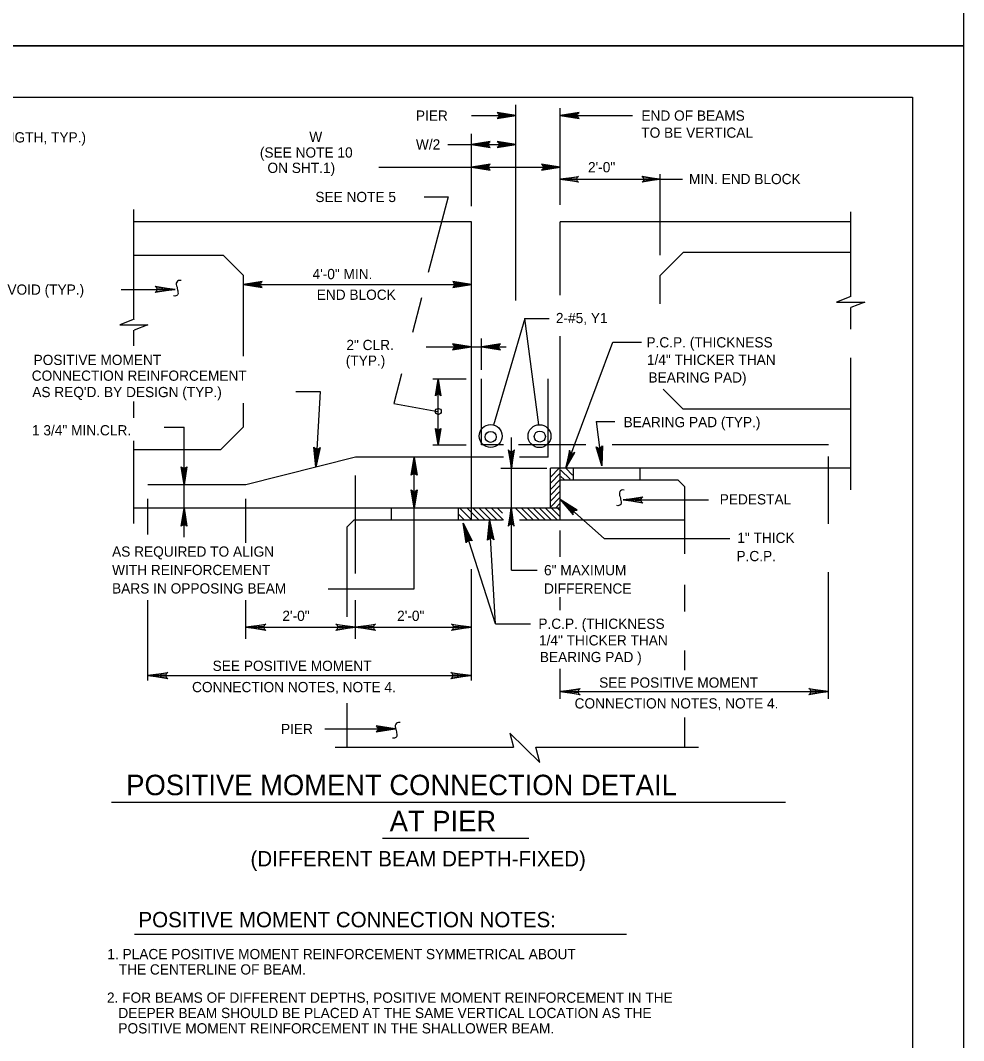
# Model space of a CAD drawing. Extents: x 641517 to 642372, y 298537 to 300319.
# Drawn here: x 642081.6 to 642358, y 299433 to 299732.1 of the extents above; entities that cross this region are included whole.
import ezdxf

# ---------------------------------------------------------------- set-up
doc = ezdxf.new("R2010")
doc.units = 0
for name, color, linetype in [('1', 7, 'Continuous'), ('2', 7, 'Continuous'), ('3', 7, 'Continuous'), ('PLT-BNDY', 7, 'Continuous')]:
    doc.layers.add(name, color=color, linetype=linetype)

msp = doc.modelspace()

# ---------------------------------------------------------------- linework, layer by layer
at = {"layer": '1'}
for p, q in [((642226.83, 299649.99), (642226.83, 299707.41)), ((642213.81, 299589.15), (642213.81, 299673.03)), ((642239.85, 299651.6), (642239.85, 299673.03)), ((642233.55, 299613.6), (642229.43, 299644.7)), ((642239.85, 299585.63), (642239.85, 299639.58)), ((642243.69, 299597.3), (642243.69, 299600.82)), ((642210.01, 299585.63), (642210.01, 299589.15)), ((642213.81, 299585.63), (642213.81, 299589.15)), ((642233.85, 299514.6), (642225.01, 299523.13)), ((642225.01, 299523.13), (642226.17, 299519.07)), ((642233.85, 299514.6), (642232.66, 299519.07))]:
    msp.add_line(p, q, dxfattribs=at)
for points in [[(642128.69, 299655.9), (642127.89, 299655.83), (642127.45, 299655.42), (642127.28, 299654.66), (642127.5, 299653.94), (642127.65, 299653.18), (642127.78, 299652.42), (642127.69, 299651.66), (642127.13, 299651.33), (642126.52, 299651.33)], [(642258.57, 299594.44), (642257.76, 299594.38), (642257.33, 299593.96), (642257.15, 299593.2), (642257.37, 299592.48), (642257.52, 299591.72), (642257.65, 299590.96), (642257.57, 299590.2), (642257, 299589.87), (642256.39, 299589.87)], [(642192.86, 299526.3), (642192.05, 299526.23), (642191.62, 299525.82), (642191.44, 299525.06), (642191.66, 299524.34), (642191.81, 299523.58), (642191.94, 299522.82), (642191.86, 299522.06), (642191.29, 299521.73), (642190.68, 299521.73)]]:
    msp.add_spline(points, degree=3, dxfattribs=at)
at = {"layer": '2'}
for p, q in [((641557.05, 299709.62), (642343.05, 299709.62)), ((642343.05, 299709.62), (642343.05, 299145.62)), ((642239.85, 299678.05), (642239.85, 299706.36)), ((642213.81, 299704.23), (642226.83, 299704.23)), ((642239.85, 299704.29), (642261.01, 299704.29)), ((642213.81, 299677.62), (642213.81, 299698.86)), ((642206.84, 299695.76), (642213.81, 299695.76)), ((642213.81, 299695.76), (642226.83, 299695.76)), ((642186.65, 299689.09), (642213.81, 299689.09)), ((642213.81, 299689.09), (642239.85, 299689.09)), ((642239.85, 299685.55), (642269.16, 299685.55)), ((642269.16, 299663.28), (642269.16, 299687.01)), ((642269.16, 299685.55), (642275.68, 299685.55)), ((642199.98, 299680.36), (642206.95, 299680.36)), ((642206.95, 299680.36), (642201.13, 299658.24)), ((642114.85, 299644.49), (642114.85, 299676.71)), ((642325.02, 299651.18), (642325.02, 299675.97)), ((642213.81, 299673.03), (642114.85, 299673.03)), ((642325.02, 299673.03), (642239.85, 299673.03)), ((642141.1, 299663.19), (642114.85, 299663.19)), ((642275.88, 299664.05), (642269.16, 299657.33)), ((642325.02, 299664.05), (642275.88, 299664.05)), ((642111.18, 299653.26), (642126.94, 299653.26)), ((642146.96, 299654.66), (642213.81, 299654.66)), ((642199.17, 299650.79), (642196.5, 299640.63)), ((642325.02, 299651.18), (642320.84, 299649.54)), ((642320.84, 299649.54), (642329.08, 299649.54)), ((642329.08, 299649.54), (642325.02, 299647.96)), ((642324.97, 299641.62), (642324.97, 299647.96)), ((642114.92, 299644.49), (642110.74, 299642.85)), ((642229.43, 299644.7), (642220.31, 299613.49)), ((642229.43, 299644.7), (642236.55, 299644.7)), ((642110.74, 299642.85), (642118.98, 299642.85)), ((642114.85, 299636.69), (642114.85, 299641.27)), ((642118.98, 299642.85), (642114.92, 299641.27)), ((642216.78, 299629.66), (642216.78, 299638.89)), ((642241.5, 299600.82), (642255.25, 299637.78)), ((642255.25, 299637.78), (642263.69, 299637.78)), ((642200.49, 299636.42), (642213.81, 299636.42)), ((642213.81, 299636.42), (642224, 299636.42)), ((642324.97, 299594.5), (642324.97, 299633.19)), ((642193.32, 299628.52), (642191.02, 299619.78)), ((642202.46, 299627), (642212.23, 299627)), ((642204.07, 299607.67), (642204.07, 299626.95)), ((642216.78, 299607.67), (642216.78, 299627)), ((642236.32, 299604.1), (642236.32, 299627)), ((642162.31, 299623.33), (642169.49, 299623.33)), ((642169.49, 299623.33), (642168.19, 299601.13)), ((642114.85, 299615.56), (642114.85, 299620.38)), ((642191.02, 299619.78), (642203.91, 299617.49)), ((642324.97, 299618.12), (642275.88, 299618.12)), ((642250.32, 299614.51), (642255.85, 299614.51)), ((642250.32, 299614.51), (642252, 299601.49)), ((642123.72, 299612.84), (642129.55, 299612.84)), ((642129.55, 299595.94), (642129.55, 299612.84)), ((642146.96, 299612.92), (642140.24, 299606.2)), ((642114.85, 299584.59), (642114.85, 299608.9)), ((642202.46, 299607.67), (642212.23, 299607.67)), ((642223.2, 299607.67), (642216.78, 299607.67)), ((642225.5, 299600.73), (642225.5, 299609.81)), ((642247.28, 299607.67), (642227.6, 299607.67)), ((642318.49, 299607.67), (642255, 299607.67)), ((642140.24, 299606.2), (642114.85, 299606.2)), ((642179.86, 299604.1), (642147.71, 299595.94)), ((642223.2, 299604.1), (642179.86, 299604.1)), ((642197, 299589.15), (642197, 299604.1)), ((642236.32, 299604.1), (642227.92, 299604.1)), ((642318.49, 299584.54), (642318.49, 299604.28)), ((642179.86, 299569.98), (642179.86, 299598.7)), ((642222.43, 299600.82), (642235.91, 299600.82)), ((642225.5, 299587.94), (642225.5, 299600.73)), ((642236.93, 299589.15), (642236.93, 299600.82)), ((642324.97, 299600.82), (642236.93, 299600.82)), ((642239.55, 299600.82), (642236.93, 299598.2)), ((642239.85, 299599.35), (642236.93, 299596.43)), ((642242.69, 299597.62), (642240.01, 299600.3)), ((642243.41, 299598.83), (642241.42, 299600.82)), ((642263.29, 299597.3), (642263.29, 299600.82)), ((642147.71, 299595.94), (642118.99, 299595.94)), ((642129.55, 299589.15), (642129.55, 299595.94)), ((642239.85, 299597.56), (642236.93, 299594.63)), ((642239.85, 299595.91), (642236.93, 299592.98)), ((642274.36, 299597.3), (642239.85, 299597.3)), ((642240.95, 299597.48), (642240.04, 299598.39)), ((642276.31, 299595.34), (642274.36, 299597.3)), ((642239.85, 299594.14), (642236.93, 299591.22)), ((642276.31, 299575.69), (642276.31, 299595.34)), ((642118.99, 299581.37), (642118.99, 299591.83)), ((642147.71, 299578.99), (642147.71, 299591.83)), ((642239.85, 299592.37), (642236.63, 299589.15)), ((642239.85, 299590.61), (642238.4, 299589.15)), ((642239.85, 299591.7), (642252.69, 299580.18)), ((642258.24, 299591.54), (642283.31, 299591.54)), ((642239.85, 299589.15), (642114.85, 299589.15)), ((642129.55, 299580.65), (642129.55, 299589.15)), ((642190.38, 299585.63), (642190.38, 299589.15)), ((642197, 299565.45), (642197, 299589.15)), ((642211.79, 299585.63), (642210.14, 299587.27)), ((642213.93, 299585.63), (642210.52, 299589.04)), ((642216.08, 299585.63), (642212.55, 299589.15)), ((642217.84, 299585.63), (642214.32, 299589.15)), ((642219.61, 299585.63), (642216.09, 299589.15)), ((642221.38, 299585.63), (642217.86, 299589.15)), ((642223.15, 299585.63), (642219.63, 299589.15)), ((642222.89, 299587.66), (642221.39, 299589.15)), ((642225.5, 299570.98), (642225.5, 299587.94)), ((642230.22, 299585.63), (642226.7, 299589.15)), ((642231.98, 299585.63), (642228.46, 299589.15)), ((642233.75, 299585.63), (642230.23, 299589.15)), ((642235.52, 299585.63), (642232, 299589.15)), ((642237.29, 299585.63), (642233.77, 299589.15)), ((642239.06, 299585.63), (642235.54, 299589.15)), ((642239.85, 299586.6), (642237.3, 299589.15)), ((642239.85, 299588.37), (642239.07, 299589.15)), ((642177.35, 299583.67), (642179.31, 299585.63)), ((642177.35, 299557.28), (642177.35, 299583.67)), ((642222.88, 299585.63), (642179.31, 299585.63)), ((642220.89, 299555.22), (642211.35, 299584.75)), ((642220.89, 299555.22), (642219.13, 299585.63)), ((642276.31, 299585.63), (642227.92, 299585.63)), ((642239.85, 299574.81), (642239.85, 299582.6)), ((642252.69, 299580.18), (642289.49, 299580.18)), ((642213.81, 299538.61), (642213.81, 299571.23)), ((642225.5, 299570.98), (642233.07, 299570.98)), ((642318.49, 299533.24), (642318.49, 299570.4)), ((642276.31, 299558.78), (642276.31, 299566.65)), ((642171.84, 299565.45), (642197, 299565.45)), ((642239.85, 299559.21), (642239.85, 299563.07)), ((642118.99, 299538.61), (642118.99, 299562.13)), ((642147.71, 299550.84), (642147.71, 299562.13)), ((642179.86, 299550.84), (642179.86, 299562.13)), ((642147.71, 299554.21), (642179.86, 299554.21)), ((642179.86, 299554.21), (642213.81, 299554.21)), ((642220.89, 299555.22), (642231.11, 299555.22)), ((642276.31, 299541.61), (642276.31, 299547.41)), ((642239.85, 299533.24), (642239.85, 299542.04)), ((642118.99, 299540.05), (642213.6, 299540.05)), ((642239.85, 299535.33), (642318.49, 299535.33)), ((642177.35, 299519.07), (642177.35, 299531.95)), ((642276.31, 299519.07), (642276.31, 299527.73)), ((642170.86, 299524.43), (642191.41, 299524.43)), ((642173.82, 299519.07), (642226.17, 299519.07)), ((642232.66, 299519.07), (642280.38, 299519.07)), ((642108.26, 299502.92), (642305.88, 299502.92)), ((642187.71, 299492.33), (642230.64, 299492.33)), ((642115, 299464.27), (642259.25, 299464.27))]:
    msp.add_line(p, q, dxfattribs=at)
for points in [[(642221.6, 299703.57), (642221.8, 299703.95), (642226.83, 299704.23), (642221.6, 299703.57), (642221.33, 299703.34), (642226.83, 299704.23), (642221.8, 299704.47), (642221.62, 299704.85), (642226.83, 299704.23), (642221.33, 299705.1), (642221.62, 299704.85)], [(642245.08, 299704.94), (642244.89, 299704.56), (642239.85, 299704.29), (642245.08, 299704.94), (642245.35, 299705.17), (642239.85, 299704.29), (642244.89, 299704.04), (642245.07, 299703.66), (642239.85, 299704.29), (642245.35, 299703.41), (642245.07, 299703.66)], [(642219.04, 299696.42), (642218.85, 299696.04), (642213.81, 299695.76), (642219.04, 299696.42), (642219.31, 299696.64), (642213.81, 299695.76), (642218.84, 299695.51), (642219.03, 299695.13), (642213.81, 299695.76), (642219.31, 299694.88), (642219.03, 299695.13)], [(642221.6, 299695.1), (642221.8, 299695.48), (642226.83, 299695.76), (642221.6, 299695.1), (642221.33, 299694.87), (642226.83, 299695.76), (642221.8, 299696.01), (642221.62, 299696.38), (642226.83, 299695.76), (642221.33, 299696.63), (642221.62, 299696.38)], [(642219.04, 299689.75), (642218.85, 299689.37), (642213.81, 299689.09), (642219.04, 299689.75), (642219.31, 299689.98), (642213.81, 299689.09), (642218.84, 299688.84), (642219.03, 299688.47), (642213.81, 299689.09), (642219.31, 299688.22), (642219.03, 299688.47)], [(642234.62, 299688.43), (642234.82, 299688.81), (642239.85, 299689.09), (642234.62, 299688.43), (642234.35, 299688.21), (642239.85, 299689.09), (642234.82, 299689.34), (642234.64, 299689.72), (642239.85, 299689.09), (642234.35, 299689.97), (642234.64, 299689.72)], [(642244.93, 299684.92), (642244.74, 299685.28), (642239.85, 299685.55), (642244.93, 299684.92), (642245.19, 299684.69), (642239.85, 299685.55), (642244.73, 299685.8), (642244.91, 299686.16), (642239.85, 299685.55), (642245.19, 299686.4), (642244.91, 299686.16)], [(642264.08, 299686.19), (642264.27, 299685.82), (642269.16, 299685.55), (642264.08, 299686.19), (642263.82, 299686.41), (642269.16, 299685.55), (642264.28, 299685.31), (642264.1, 299684.95), (642269.16, 299685.55), (642263.82, 299684.71), (642264.1, 299684.95)], [(642152.2, 299655.32), (642152, 299654.94), (642146.96, 299654.66), (642152.2, 299655.32), (642152.46, 299655.55), (642146.96, 299654.66), (642152, 299654.41), (642152.18, 299654.04), (642146.96, 299654.66), (642152.46, 299653.79), (642152.18, 299654.04)], [(642208.58, 299654), (642208.78, 299654.38), (642213.81, 299654.66), (642208.58, 299654), (642208.31, 299653.77), (642213.81, 299654.66), (642208.78, 299654.91), (642208.6, 299655.28), (642213.81, 299654.66), (642208.31, 299655.54), (642208.6, 299655.28)], [(642121.41, 299653.96), (642121.61, 299653.56), (642126.94, 299653.26), (642121.41, 299653.96), (642121.12, 299654.2), (642126.94, 299653.26), (642121.62, 299653), (642121.42, 299652.6), (642126.94, 299653.26), (642121.12, 299652.34), (642121.42, 299652.6)], [(642208.47, 299635.77), (642208.67, 299636.15), (642213.7, 299636.43), (642208.47, 299635.77), (642208.2, 299635.55), (642213.7, 299636.43), (642208.67, 299636.68), (642208.49, 299637.06), (642213.7, 299636.43), (642208.2, 299637.31), (642208.49, 299637.06)], [(642222.07, 299637.06), (642221.88, 299636.69), (642216.84, 299636.41), (642222.07, 299637.06), (642222.34, 299637.29), (642216.84, 299636.41), (642221.87, 299636.16), (642222.06, 299635.78), (642216.84, 299636.41), (642222.34, 299635.53), (642222.06, 299635.78)], [(642203.49, 299622.34), (642203.83, 299622.51), (642204.07, 299626.95), (642203.49, 299622.34), (642203.29, 299622.1), (642204.07, 299626.95), (642204.29, 299622.52), (642204.62, 299622.35), (642204.07, 299626.95), (642204.84, 299622.1), (642204.62, 299622.35)], [(642204.65, 299612.28), (642204.32, 299612.11), (642204.07, 299607.67), (642204.65, 299612.28), (642204.85, 299612.52), (642204.07, 299607.67), (642203.85, 299612.11), (642203.52, 299612.27), (642204.07, 299607.67), (642203.3, 299612.52), (642203.52, 299612.27)], [(642169.21, 299606.62), (642168.8, 299606.44), (642168.19, 299601.13), (642169.21, 299606.62), (642169.47, 299606.89), (642168.19, 299601.13), (642168.24, 299606.47), (642167.85, 299606.68), (642168.19, 299601.13), (642167.61, 299607), (642167.85, 299606.68)], [(642224.84, 299605.96), (642225.22, 299605.77), (642225.5, 299600.73), (642224.84, 299605.96), (642224.61, 299606.23), (642225.5, 299600.73), (642225.75, 299605.76), (642226.12, 299605.95), (642225.5, 299600.73), (642226.37, 299606.23), (642226.12, 299605.95)], [(642242.66, 299605.76), (642242.94, 299605.46), (642241.5, 299600.82), (642242.66, 299605.76), (642242.54, 299606.08), (642241.5, 299600.82), (642243.41, 299605.28), (642243.81, 299605.32), (642241.5, 299600.82), (642244.13, 299605.49), (642243.81, 299605.32)], [(642251.98, 299607.07), (642251.61, 299606.81), (642252, 299601.49), (642251.98, 299607.07), (642252.18, 299607.38), (642252, 299601.49), (642251.05, 299606.74), (642250.64, 299606.88), (642252, 299601.49), (642250.34, 299607.14), (642250.64, 299606.88)], [(642196.36, 299599.02), (642196.73, 299599.21), (642197, 299604.1), (642196.36, 299599.02), (642196.14, 299598.76), (642197, 299604.1), (642197.24, 299599.21), (642197.6, 299599.04), (642197, 299604.1), (642197.85, 299598.76), (642197.6, 299599.04)], [(642130.19, 299601.01), (642129.82, 299600.83), (642129.55, 299595.94), (642130.19, 299601.01), (642130.41, 299601.27), (642129.55, 299595.94), (642129.31, 299600.82), (642128.94, 299601), (642129.55, 299595.94), (642128.7, 299601.27), (642128.94, 299601)], [(642197.64, 299594.22), (642197.27, 299594.04), (642197, 299589.15), (642197.64, 299594.22), (642197.86, 299594.48), (642197, 299589.15), (642196.76, 299594.03), (642196.4, 299594.21), (642197, 299589.15), (642196.15, 299594.48), (642196.4, 299594.21)], [(642244.44, 299588.52), (642244.01, 299588.36), (642239.85, 299591.7), (642244.44, 299588.52), (642244.81, 299588.51), (642239.85, 299591.7), (642243.64, 299587.95), (642243.52, 299587.52), (642239.85, 299591.7), (642243.57, 299587.13), (642243.52, 299587.52)], [(642263.78, 299590.85), (642263.57, 299591.25), (642258.24, 299591.54), (642263.78, 299590.85), (642264.06, 299590.6), (642258.24, 299591.54), (642263.57, 299591.81), (642263.76, 299592.2), (642258.24, 299591.54), (642264.06, 299592.47), (642263.76, 299592.2)], [(642128.91, 299584.08), (642129.28, 299584.27), (642129.55, 299589.15), (642128.91, 299584.08), (642128.69, 299583.82), (642129.55, 299589.15), (642129.79, 299584.27), (642130.15, 299584.09), (642129.55, 299589.15), (642130.4, 299583.82), (642130.15, 299584.09)], [(642226.09, 299584.11), (642225.71, 299584.31), (642225.43, 299589.35), (642226.09, 299584.11), (642226.32, 299583.85), (642225.43, 299589.35), (642225.18, 299584.31), (642224.81, 299584.13), (642225.43, 299589.35), (642224.56, 299583.85), (642224.81, 299584.13)], [(642212.39, 299579.27), (642212.71, 299579.59), (642211.35, 299584.75), (642212.39, 299579.27), (642212.25, 299578.92), (642211.35, 299584.75), (642213.24, 299579.76), (642213.67, 299579.7), (642211.35, 299584.75), (642214.02, 299579.5), (642213.67, 299579.7)], [(642218.76, 299580.06), (642219.15, 299580.29), (642219.13, 299585.63), (642218.76, 299580.06), (642218.53, 299579.77), (642219.13, 299585.63), (642219.7, 299580.33), (642220.11, 299580.16), (642219.13, 299585.63), (642220.39, 299579.87), (642220.11, 299580.16)], [(642153.25, 299553.52), (642153.04, 299553.92), (642147.71, 299554.21), (642153.25, 299553.52), (642153.53, 299553.27), (642147.71, 299554.21), (642153.04, 299554.48), (642153.23, 299554.87), (642147.71, 299554.21), (642153.53, 299555.14), (642153.23, 299554.87)], [(642174.33, 299554.91), (642174.53, 299554.51), (642179.86, 299554.21), (642174.33, 299554.91), (642174.04, 299555.15), (642179.86, 299554.21), (642174.54, 299553.95), (642174.34, 299553.55), (642179.86, 299554.21), (642174.04, 299553.29), (642174.34, 299553.55)], [(642185.4, 299553.52), (642185.19, 299553.92), (642179.86, 299554.21), (642185.4, 299553.52), (642185.68, 299553.27), (642179.86, 299554.21), (642185.19, 299554.48), (642185.38, 299554.87), (642179.86, 299554.21), (642185.68, 299555.14), (642185.38, 299554.87)], [(642208.28, 299554.91), (642208.48, 299554.51), (642213.81, 299554.21), (642208.28, 299554.91), (642207.99, 299555.15), (642213.81, 299554.21), (642208.49, 299553.95), (642208.29, 299553.55), (642213.81, 299554.21), (642207.99, 299553.29), (642208.29, 299553.55)], [(642124.52, 299539.35), (642124.32, 299539.75), (642118.99, 299540.05), (642124.52, 299539.35), (642124.81, 299539.11), (642118.99, 299540.05), (642124.31, 299540.31), (642124.51, 299540.71), (642118.99, 299540.05), (642124.81, 299540.97), (642124.51, 299540.71)], [(642208.06, 299540.74), (642208.27, 299540.34), (642213.6, 299540.05), (642208.06, 299540.74), (642207.78, 299540.99), (642213.6, 299540.05), (642208.27, 299539.78), (642208.08, 299539.39), (642213.6, 299540.05), (642207.78, 299539.12), (642208.08, 299539.39)], [(642245.39, 299534.63), (642245.18, 299535.03), (642239.85, 299535.33), (642245.39, 299534.63), (642245.67, 299534.39), (642239.85, 299535.33), (642245.18, 299535.59), (642245.37, 299535.99), (642239.85, 299535.33), (642245.67, 299536.25), (642245.37, 299535.99)], [(642312.96, 299536.02), (642313.16, 299535.62), (642318.49, 299535.33), (642312.96, 299536.02), (642312.67, 299536.26), (642318.49, 299535.33), (642313.17, 299535.06), (642312.97, 299534.67), (642318.49, 299535.33), (642312.67, 299534.4), (642312.97, 299534.67)], [(642186.18, 299523.77), (642186.37, 299524.15), (642191.41, 299524.43), (642186.18, 299523.77), (642185.91, 299523.54), (642191.41, 299524.43), (642186.38, 299524.68), (642186.19, 299525.05), (642191.41, 299524.43), (642185.91, 299525.3), (642186.19, 299525.05)]]:
    msp.add_lwpolyline(points, dxfattribs=at)
for centre, radius in [((642204.1, 299617.49), 0.866), ((642219.43, 299610.25), 3.36), ((642233.74, 299610.24), 3.36), ((642219.43, 299610.02), 1.62), ((642233.84, 299610.12), 1.62)]:
    msp.add_circle(centre, radius, dxfattribs=at)
at = {"layer": '3'}
for p, q in [((642146.96, 299657.33), (642141.1, 299663.19)), ((642146.96, 299633.68), (642146.96, 299657.33)), ((642269.16, 299649.07), (642269.16, 299657.33)), ((642275.88, 299618.12), (642270.01, 299623.99)), ((642146.96, 299612.92), (642146.96, 299619.95))]:
    msp.add_line(p, q, dxfattribs=at)
at = {"layer": 'PLT-BNDY'}
for points in [[(641517.05, 300318.62), (642358.05, 300318.62), (642358.05, 299724.62), (641517.05, 299724.62)], [(641517.05, 299724.62), (642358.05, 299724.62), (642358.05, 299130.62), (641517.05, 299130.62)]]:
    msp.add_lwpolyline(points, close=True, dxfattribs=at)

# ---------------------------------------------------------------- texts
at = {"layer": '2'}
for s, height, p in [('(TENSION DEVELOPMENT LENGTH, TYP.)', 3, (642020.36, 299696.34)), ('(SEE NOTE 10', 3, (642151.78, 299691.9)), ('  ON SHT.1)', 3, (642151.78, 299687.4)), ('SEE NOTE 5', 3, (642168.05, 299678.86)), ('1 3/4" MIN.CLR.', 3, (642084.99, 299610.46)), ('AS REQUIRED TO ALIGN', 3, (642108.47, 299574.9)), ('WITH REINFORCEMENT', 3, (642108.47, 299569.5)), ('BARS IN OPPOSING BEAM', 3, (642108.47, 299564.1)), ('2\'-0"', 3, (642158.38, 299556.06)), ('2\'-0"', 3, (642192.01, 299556.06)), ('SEE POSITIVE MOMENT', 3, (642137.94, 299541.41)), ('SEE POSITIVE MOMENT', 3, (642251.23, 299536.49)), ('CONNECTION NOTES, NOTE 4.', 3, (642131.91, 299535.17)), ('CONNECTION NOTES, NOTE 4.', 3, (642244.03, 299530.39)), ('POSITIVE MOMENT CONNECTION DETAIL', 6, (642112.62, 299504.97)), ('AT PIER', 6, (642189.84, 299494.39)), ('(DIFFERENT BEAM DEPTH-FIXED)', 4.5, (642149.04, 299484.1)), ('POSITIVE MOMENT CONNECTION NOTES:', 4.5, (642116.2, 299466.24)), ('1. PLACE POSITIVE MOMENT REINFORCEMENT SYMMETRICAL ABOUT', 3, (642107.08, 299456.89)), ('   THE CENTERLINE OF BEAM.', 3, (642107.08, 299452.39)), ('2. FOR BEAMS OF DIFFERENT DEPTHS, POSITIVE MOMENT REINFORCEMENT IN THE', 3, (642106.97, 299444.12)), ('   DEEPER BEAM SHOULD BE PLACED AT THE SAME VERTICAL LOCATION AS THE', 3, (642106.97, 299439.62)), ('   POSITIVE MOMENT REINFORCEMENT IN THE SHALLOWER BEAM.', 3, (642106.97, 299435.12))]:
    msp.add_text(s, height=height, dxfattribs=at).set_placement(p)
at = {"layer": '3'}
for s, height, p in [('  PIER', 2.999, (642195.29, 299702.72)), ('END OF BEAMS', 2.9989, (642263.61, 299702.72)), ('TO BE VERTICAL', 2.9989, (642263.58, 299697.72)), ('W', 3, (642166.28, 299696.48)), ('W/2', 2.997, (642197.53, 299694.27)), ('2\'-0"', 2.997, (642247.96, 299687.59)), ('MIN. END BLOCK', 2.9968, (642277.56, 299684.12)), ('4\'-0" MIN.', 2.997, (642167.22, 299656.26)), ('VOID (TYP.)', 2.9968, (642077.79, 299651.71)), ('END BLOCK', 2.997, (642168.46, 299650.2)), ('2-#5, Y1', 2.997, (642238.55, 299643.37)), ('2" CLR.', 2.997, (642177.15, 299635.47)), ('P.C.P. (THICKNESS ', 2.9989, (642265.09, 299636.24)), ('POSITIVE MOMENT', 2.9968, (642085.46, 299631.09)), ('(TYP.)', 2.997, (642176.97, 299630.88)), ('1/4" THICKER THAN', 2.9989, (642265.22, 299631.13)), ('CONNECTION REINFORCEMENT', 2.9968, (642084.92, 299626.47)), ('BEARING PAD)', 2.9989, (642265.68, 299625.94)), ("AS REQ'D. BY DESIGN (TYP.)", 2.9968, (642085.08, 299621.67)), ('BEARING PAD (TYP.)', 2.9989, (642258.39, 299612.85)), ('PEDESTAL', 2.999, (642286.57, 299590.21)), ('1" THICK', 2.999, (642291.71, 299578.93)), ('P.C.P.', 2.999, (642291.47, 299573.58)), ('6" MAXIMUM', 2.999, (642235.07, 299569.45)), ('DIFFERENCE', 2.999, (642235.07, 299564.05)), ('P.C.P. (THICKNESS ', 2.9989, (642233.42, 299553.74)), ('1/4" THICKER THAN', 2.9989, (642233.6, 299548.88)), ('BEARING PAD )', 2.9989, (642233.84, 299543.98)), ('PIER', 2.999, (642157.97, 299522.87))]:
    msp.add_text(s, height=height, dxfattribs=at).set_placement(p)

doc.saveas('drawing.dxf')
